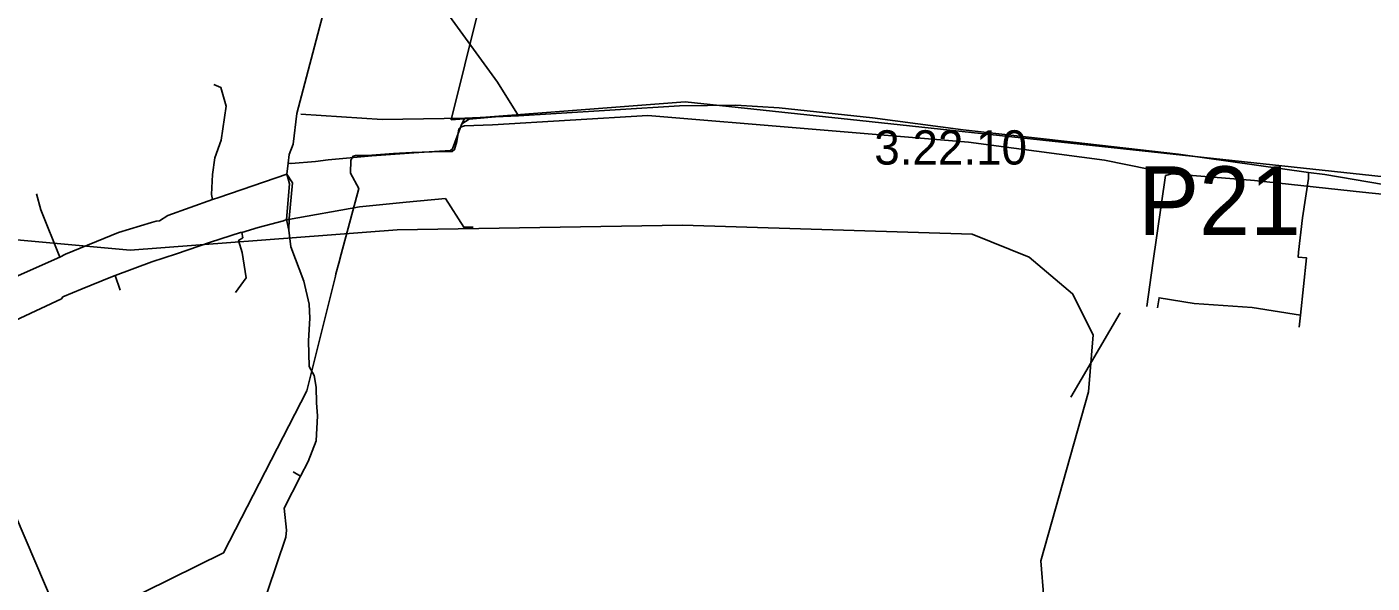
# Model space of a CAD drawing. Extents: x -662500 to -655523, y -1056000 to -1049993.
# Drawn here: x -659980.6 to -659685.9, y -1052099.4 to -1051977.6 of the extents above; entities that cross this region are included whole.
import ezdxf

# ---------------------------------------------------------------- set-up
doc = ezdxf.new("R2010")
doc.units = 0
for name, color, linetype in [('Vrstva 24', 7, 'Continuous'), ('Vrstva 45', 7, 'Continuous'), ('Vrstva 48', 7, 'Continuous'), ('Vrstva 61', 7, 'Continuous')]:
    doc.layers.add(name, color=color, linetype=linetype)

msp = doc.modelspace()

# ---------------------------------------------------------------- linework, layer by layer
at = {"layer": 'Vrstva 24'}
msp.add_lwpolyline([(-659753.8, -1052131.2), (-659756.5, -1052119), (-659758.5, -1052094.5), (-659748, -1052057.5), (-659747, -1052045), (-659751.5, -1052036), (-659761, -1052028), (-659773.5, -1052023), (-659837, -1052021), (-659899.5, -1052022), (-659958, -1052026.5), (-659996.5, -1052023), (-660000, -1052023), (-660013, -1052023)], dxfattribs=at)
at = {"layer": 'Vrstva 45'}
for p, q in [((-659884.7, -1051997.54), (-659872.93, -1051997.03)), ((-659884.7, -1051997.54), (-659872.93, -1051997.03)), ((-659872.93, -1051997.03), (-659865.86, -1051996.6)), ((-659872.93, -1051997.03), (-659865.86, -1051996.6)), ((-659872.93, -1051997.03), (-659865.86, -1051996.6)), ((-659872.93, -1051997.03), (-659865.86, -1051996.6)), ((-659872.93, -1051997.03), (-659865.86, -1051996.6)), ((-659872.93, -1051997.03), (-659865.86, -1051996.6)), ((-659884.7, -1051997.54), (-659885.32, -1051998.78)), ((-659884.7, -1051997.54), (-659885.32, -1051998.78)), ((-659884.75, -1051999.23), (-659878.58, -1051999.04)), ((-659884.75, -1051999.23), (-659878.58, -1051999.04)), ((-659895.81, -1052005.18), (-659890.25, -1052004.78)), ((-659895.81, -1052005.18), (-659890.25, -1052004.78)), ((-659923.68, -1052009.86), (-659923.4, -1052007.4)), ((-659923.68, -1052009.86), (-659923.4, -1052007.4)), ((-659923.68, -1052009.86), (-659923.4, -1052007.4)), ((-659923.68, -1052009.86), (-659923.4, -1052007.4)), ((-659917.4, -1052007.06), (-659922.75, -1052007.52)), ((-659917.4, -1052007.06), (-659922.75, -1052007.52)), ((-659923.12, -1052011.97), (-659923.72, -1052019.76)), ((-659923.12, -1052011.97), (-659923.72, -1052019.76)), ((-659923.41, -1052010.89), (-659923.68, -1052009.86)), ((-659923.41, -1052010.89), (-659923.68, -1052009.86)), ((-659922.46, -1052011.76), (-659923.17, -1052019.57)), ((-659922.46, -1052011.76), (-659923.17, -1052019.57)), ((-659699.84, -1052009.5), (-659696.21, -1052009.89)), ((-659699.84, -1052009.5), (-659696.21, -1052009.89)), ((-659699.84, -1052009.5), (-659696.21, -1052009.89)), ((-659699.84, -1052009.5), (-659696.21, -1052009.89)), ((-659699.84, -1052009.5), (-659696.21, -1052009.89)), ((-659699.84, -1052009.5), (-659696.21, -1052009.89)), ((-659960.58, -1052022.64), (-659953.35, -1052020.43)), ((-659960.58, -1052022.64), (-659953.35, -1052020.43)), ((-659923.28, -1052019.74), (-659923.72, -1052019.76)), ((-659923.28, -1052019.74), (-659923.72, -1052019.76)), ((-659923.72, -1052019.76), (-659923.23, -1052022.1)), ((-659923.72, -1052019.76), (-659923.23, -1052022.1)), ((-659701.15, -1052019.39), (-659702.01, -1052026.9)), ((-659701.15, -1052019.39), (-659702.01, -1052026.9)), ((-659940.39, -1052024.69), (-659933.85, -1052022.64)), ((-659940.39, -1052024.69), (-659933.85, -1052022.64)), ((-659953.23, -1052029.03), (-659947.88, -1052027.26)), ((-659953.23, -1052029.03), (-659947.88, -1052027.26)), ((-659912.3, -1052029.31), (-659911.76, -1052027.33)), ((-659912.3, -1052029.31), (-659911.76, -1052027.33)), ((-659968.48, -1052034.94), (-659962.26, -1052032.36)), ((-659968.48, -1052034.94), (-659962.26, -1052032.36)), ((-659961.3, -1052032.01), (-659960.16, -1052035.22)), ((-659961.3, -1052032.01), (-659960.16, -1052035.22)), ((-659751.87, -1052058.63), (-659741.12, -1052040.18)), ((-659751.87, -1052058.63), (-659741.12, -1052040.18)), ((-659701.87, -1052043.31), (-659701.59, -1052040.7)), ((-659701.87, -1052043.31), (-659701.59, -1052040.7)), ((-659922.31, -1052075.01), (-659920.64, -1052075.93)), ((-659922.31, -1052075.01), (-659920.64, -1052075.93))]:
    msp.add_line(p, q, dxfattribs=at)
for points in [[(-659921.51, -1051996.53), (-659915.5, -1051973.85), (-659913.41, -1051968.41), (-659910.3, -1051949.92), (-659910.26, -1051947.71)], [(-659921.51, -1051996.53), (-659915.5, -1051973.85), (-659913.41, -1051968.41), (-659910.3, -1051949.92), (-659910.26, -1051947.71)], [(-659899.23, -1051960.87), (-659898.67, -1051961.69), (-659888.06, -1051975.22), (-659877.52, -1051989.69), (-659872.93, -1051997.03)], [(-659899.23, -1051960.87), (-659898.67, -1051961.69), (-659888.06, -1051975.22), (-659877.52, -1051989.69), (-659872.93, -1051997.03)], [(-659899.23, -1051960.87), (-659898.67, -1051961.69), (-659888.06, -1051975.22), (-659877.52, -1051989.69), (-659872.93, -1051997.03)], [(-659899.23, -1051960.87), (-659898.67, -1051961.69), (-659888.06, -1051975.22), (-659877.52, -1051989.69), (-659872.93, -1051997.03)], [(-659939.92, -1052015.39), (-659940.14, -1052014.26), (-659939.96, -1052009.89), (-659939.41, -1052006.28), (-659938.03, -1052002.37), (-659936.97, -1051994.97), (-659938.15, -1051990.83), (-659939.7, -1051990.23)], [(-659939.92, -1052015.39), (-659940.14, -1052014.26), (-659939.96, -1052009.89), (-659939.41, -1052006.28), (-659938.03, -1052002.37), (-659936.97, -1051994.97), (-659938.15, -1051990.83), (-659939.7, -1051990.23)], [(-659923.4, -1052007.4), (-659923.13, -1052005.54), (-659922.3, -1052003.3), (-659921.51, -1051996.53)], [(-659923.4, -1052007.4), (-659923.13, -1052005.54), (-659922.3, -1052003.3), (-659921.51, -1051996.53)], [(-659920.6, -1051996.72), (-659902.81, -1051997.88), (-659884.7, -1051997.54)], [(-659920.6, -1051996.72), (-659902.81, -1051997.88), (-659884.7, -1051997.54)], [(-659870.66, -1051996.6), (-659883.71, -1051997.76), (-659885.32, -1051998.78)], [(-659870.66, -1051996.6), (-659883.71, -1051997.76), (-659885.32, -1051998.78)], [(-659878.58, -1051999.04), (-659844.57, -1051997.01), (-659774.33, -1052002.82), (-659744.5, -1052006.79), (-659729.75, -1052009.73)], [(-659878.58, -1051999.04), (-659844.57, -1051997.01), (-659774.33, -1052002.82), (-659744.5, -1052006.79), (-659729.75, -1052009.73)], [(-659865.86, -1051996.6), (-659837.64, -1051994.86), (-659825.32, -1051994.73), (-659815.8, -1051995.33), (-659795.38, -1051997.48), (-659775.52, -1052000.1), (-659751.37, -1052002.82), (-659728.29, -1052005.43), (-659699.84, -1052009.5)], [(-659865.86, -1051996.6), (-659837.64, -1051994.86), (-659825.32, -1051994.73), (-659815.8, -1051995.33), (-659795.38, -1051997.48), (-659775.52, -1052000.1), (-659751.37, -1052002.82), (-659728.29, -1052005.43), (-659699.84, -1052009.5)], [(-659865.86, -1051996.6), (-659837.64, -1051994.86), (-659825.32, -1051994.73), (-659815.8, -1051995.33), (-659795.38, -1051997.48), (-659775.52, -1052000.1), (-659751.37, -1052002.82), (-659728.29, -1052005.43), (-659699.84, -1052009.5)], [(-659865.86, -1051996.6), (-659837.64, -1051994.86), (-659825.32, -1051994.73), (-659815.8, -1051995.33), (-659795.38, -1051997.48), (-659775.52, -1052000.1), (-659751.37, -1052002.82), (-659728.29, -1052005.43), (-659699.84, -1052009.5)], [(-659865.86, -1051996.6), (-659837.64, -1051994.86), (-659825.32, -1051994.73), (-659815.8, -1051995.33), (-659795.38, -1051997.48), (-659775.52, -1052000.1), (-659751.37, -1052002.82), (-659728.29, -1052005.43), (-659699.84, -1052009.5)], [(-659865.86, -1051996.6), (-659837.64, -1051994.86), (-659825.32, -1051994.73), (-659815.8, -1051995.33), (-659795.38, -1051997.48), (-659775.52, -1052000.1), (-659751.37, -1052002.82), (-659728.29, -1052005.43), (-659699.84, -1052009.5)], [(-659885.32, -1051998.78), (-659886.32, -1052001.51), (-659887.35, -1052004.31), (-659887.79, -1052004.64), (-659890.25, -1052004.78), (-659895.81, -1052005.18), (-659905.06, -1052005.83), (-659914.59, -1052006.71), (-659917.4, -1052007.06), (-659922.75, -1052007.52), (-659923.4, -1052007.4)], [(-659885.32, -1051998.78), (-659886.32, -1052001.51), (-659887.35, -1052004.31), (-659887.79, -1052004.64), (-659890.25, -1052004.78), (-659895.81, -1052005.18), (-659905.06, -1052005.83), (-659914.59, -1052006.71), (-659917.4, -1052007.06), (-659922.75, -1052007.52), (-659923.4, -1052007.4)], [(-659885.32, -1051998.78), (-659886.32, -1052001.51), (-659887.35, -1052004.31), (-659887.79, -1052004.64), (-659890.25, -1052004.78), (-659895.81, -1052005.18), (-659905.06, -1052005.83), (-659914.59, -1052006.71), (-659917.4, -1052007.06), (-659922.75, -1052007.52), (-659923.4, -1052007.4)], [(-659885.32, -1051998.78), (-659886.32, -1052001.51), (-659887.35, -1052004.31), (-659887.79, -1052004.64), (-659890.25, -1052004.78), (-659895.81, -1052005.18), (-659905.06, -1052005.83), (-659914.59, -1052006.71), (-659917.4, -1052007.06), (-659922.75, -1052007.52), (-659923.4, -1052007.4)], [(-659884.75, -1051999.23), (-659885.64, -1051999.51), (-659885.95, -1051999.92), (-659886.42, -1052002.71), (-659886.95, -1052004.47), (-659887.41, -1052004.86), (-659888, -1052004.89), (-659891.85, -1052004.92), (-659896.26, -1052005.1), (-659900.28, -1052005.34), (-659905.97, -1052005.73), (-659908.63, -1052005.75), (-659909.15, -1052005.93), (-659909.68, -1052006.76), (-659909.7, -1052009.64)], [(-659884.75, -1051999.23), (-659885.64, -1051999.51), (-659885.95, -1051999.92), (-659886.42, -1052002.71), (-659886.95, -1052004.47), (-659887.41, -1052004.86), (-659888, -1052004.89), (-659891.85, -1052004.92), (-659896.26, -1052005.1), (-659900.28, -1052005.34), (-659905.97, -1052005.73), (-659908.63, -1052005.75), (-659909.15, -1052005.93), (-659909.68, -1052006.76), (-659909.7, -1052009.64)], [(-659923.68, -1052009.86), (-659938.56, -1052014.92), (-659939.92, -1052015.39)], [(-659923.68, -1052009.86), (-659938.56, -1052014.92), (-659939.92, -1052015.39)], [(-659923.72, -1052019.76), (-659923.12, -1052011.97), (-659923.41, -1052010.89)], [(-659923.72, -1052019.76), (-659923.12, -1052011.97), (-659923.41, -1052010.89)], [(-659923.23, -1052022.1), (-659923.17, -1052019.57), (-659922.46, -1052011.76), (-659923.68, -1052009.86)], [(-659923.23, -1052022.1), (-659923.17, -1052019.57), (-659922.46, -1052011.76), (-659923.68, -1052009.86)], [(-659911.76, -1052027.33), (-659907.93, -1052013), (-659909.7, -1052009.64)], [(-659911.76, -1052027.33), (-659907.93, -1052013), (-659909.7, -1052009.64)], [(-659729.75, -1052009.73), (-659731.13, -1052010.15), (-659733.95, -1052029.29), (-659735.21, -1052038.77)], [(-659729.75, -1052009.73), (-659731.13, -1052010.15), (-659733.95, -1052029.29), (-659735.21, -1052038.77)], [(-659672.38, -1052015.37), (-659688.02, -1052013.78), (-659711.64, -1052011.23), (-659729.75, -1052009.73)], [(-659672.38, -1052015.37), (-659688.02, -1052013.78), (-659711.64, -1052011.23), (-659729.75, -1052009.73)], [(-659701.59, -1052040.7), (-659700.28, -1052028.12), (-659702.1, -1052027.99), (-659702.01, -1052026.9), (-659701.15, -1052019.39), (-659699.82, -1052010.75), (-659699.84, -1052009.5)], [(-659701.59, -1052040.7), (-659700.28, -1052028.12), (-659702.1, -1052027.99), (-659702.01, -1052026.9), (-659701.15, -1052019.39), (-659699.82, -1052010.75), (-659699.84, -1052009.5)], [(-659696.21, -1052009.89), (-659683.37, -1052012.08), (-659680.79, -1052012.49), (-659675.63, -1052013.46), (-659674.22, -1052013.52), (-659653.56, -1052015.29), (-659620.75, -1052016.72), (-659579.74, -1052018.9), (-659534.75, -1052021.27), (-659514.48, -1052021.51), (-659479.83, -1052019.93)], [(-659696.21, -1052009.89), (-659683.37, -1052012.08), (-659680.79, -1052012.49), (-659675.63, -1052013.46), (-659674.22, -1052013.52), (-659653.56, -1052015.29), (-659620.75, -1052016.72), (-659579.74, -1052018.9), (-659534.75, -1052021.27), (-659514.48, -1052021.51), (-659479.83, -1052019.93)], [(-659696.21, -1052009.89), (-659683.37, -1052012.08), (-659680.79, -1052012.49), (-659675.63, -1052013.46), (-659674.22, -1052013.52), (-659653.56, -1052015.29), (-659620.75, -1052016.72), (-659579.74, -1052018.9), (-659534.75, -1052021.27), (-659514.48, -1052021.51), (-659479.83, -1052019.93)], [(-659696.21, -1052009.89), (-659683.37, -1052012.08), (-659680.79, -1052012.49), (-659675.63, -1052013.46), (-659674.22, -1052013.52), (-659653.56, -1052015.29), (-659620.75, -1052016.72), (-659579.74, -1052018.9), (-659534.75, -1052021.27), (-659514.48, -1052021.51), (-659479.83, -1052019.93)], [(-659696.21, -1052009.89), (-659683.37, -1052012.08), (-659680.79, -1052012.49), (-659675.63, -1052013.46), (-659674.22, -1052013.52), (-659653.56, -1052015.29), (-659620.75, -1052016.72), (-659579.74, -1052018.9), (-659534.75, -1052021.27), (-659514.48, -1052021.51), (-659479.83, -1052019.93)], [(-659696.21, -1052009.89), (-659683.37, -1052012.08), (-659680.79, -1052012.49), (-659675.63, -1052013.46), (-659674.22, -1052013.52), (-659653.56, -1052015.29), (-659620.75, -1052016.72), (-659579.74, -1052018.9), (-659534.75, -1052021.27), (-659514.48, -1052021.51), (-659479.83, -1052019.93)], [(-659973.41, -1052027.98), (-659977.59, -1052017.67), (-659978.53, -1052014.16)], [(-659973.41, -1052027.98), (-659977.59, -1052017.67), (-659978.53, -1052014.16)], [(-659882.82, -1052021.47), (-659884.89, -1052021.45), (-659888.91, -1052015.14), (-659897.52, -1052015.94), (-659907.73, -1052017), (-659923.28, -1052019.74)], [(-659882.82, -1052021.47), (-659884.89, -1052021.45), (-659888.91, -1052015.14), (-659897.52, -1052015.94), (-659907.73, -1052017), (-659923.28, -1052019.74)], [(-659939.92, -1052015.39), (-659949.73, -1052018.89), (-659951.54, -1052020.03), (-659952.3, -1052020.15), (-659953.35, -1052020.43), (-659960.58, -1052022.64), (-659972.18, -1052027.33), (-659973.41, -1052027.98)], [(-659939.92, -1052015.39), (-659949.73, -1052018.89), (-659951.54, -1052020.03), (-659952.3, -1052020.15), (-659953.35, -1052020.43), (-659960.58, -1052022.64), (-659972.18, -1052027.33), (-659973.41, -1052027.98)], [(-659933.53, -1052022.63), (-659929.98, -1052021.52), (-659924.42, -1052020.04), (-659923.72, -1052019.76)], [(-659933.53, -1052022.63), (-659929.98, -1052021.52), (-659924.42, -1052020.04), (-659923.72, -1052019.76)], [(-659933.53, -1052022.63), (-659933.85, -1052022.64), (-659940.39, -1052024.69), (-659947.88, -1052027.26), (-659953.23, -1052029.03), (-659961.3, -1052032.01)], [(-659933.53, -1052022.63), (-659933.85, -1052022.64), (-659940.39, -1052024.69), (-659947.88, -1052027.26), (-659953.23, -1052029.03), (-659961.3, -1052032.01)], [(-659933.53, -1052022.63), (-659933.33, -1052023.76), (-659934.25, -1052024.35), (-659933.47, -1052026.98), (-659932.6, -1052032.56), (-659934.9, -1052035.72)], [(-659933.53, -1052022.63), (-659933.33, -1052023.76), (-659934.25, -1052024.35), (-659933.47, -1052026.98), (-659932.6, -1052032.56), (-659934.9, -1052035.72)], [(-659923.23, -1052022.1), (-659922.8, -1052025.77), (-659919.91, -1052033.24), (-659918.77, -1052038.31), (-659918.6, -1052041.38), (-659918.94, -1052046.32), (-659918.76, -1052051.97), (-659917.7, -1052053.9), (-659917.21, -1052056.43), (-659917.17, -1052059.9), (-659916.92, -1052062.74), (-659917.27, -1052068.22), (-659919, -1052072.72), (-659920.64, -1052075.93)], [(-659923.23, -1052022.1), (-659922.8, -1052025.77), (-659919.91, -1052033.24), (-659918.77, -1052038.31), (-659918.6, -1052041.38), (-659918.94, -1052046.32), (-659918.76, -1052051.97), (-659917.7, -1052053.9), (-659917.21, -1052056.43), (-659917.17, -1052059.9), (-659916.92, -1052062.74), (-659917.27, -1052068.22), (-659919, -1052072.72), (-659920.64, -1052075.93)], [(-659923.23, -1052022.1), (-659922.8, -1052025.77), (-659919.91, -1052033.24), (-659918.77, -1052038.31), (-659918.6, -1052041.38), (-659918.94, -1052046.32), (-659918.76, -1052051.97), (-659917.7, -1052053.9), (-659917.21, -1052056.43), (-659917.17, -1052059.9), (-659916.92, -1052062.74), (-659917.27, -1052068.22), (-659919, -1052072.72), (-659920.64, -1052075.93)], [(-659923.23, -1052022.1), (-659922.8, -1052025.77), (-659919.91, -1052033.24), (-659918.77, -1052038.31), (-659918.6, -1052041.38), (-659918.94, -1052046.32), (-659918.76, -1052051.97), (-659917.7, -1052053.9), (-659917.21, -1052056.43), (-659917.17, -1052059.9), (-659916.92, -1052062.74), (-659917.27, -1052068.22), (-659919, -1052072.72), (-659920.64, -1052075.93)], [(-659973.41, -1052027.98), (-659985.07, -1052033.15), (-659991.06, -1052035.95), (-659998.22, -1052039.47), (-660005.46, -1052042.98)], [(-659973.41, -1052027.98), (-659985.07, -1052033.15), (-659991.06, -1052035.95), (-659998.22, -1052039.47), (-660005.46, -1052042.98)], [(-659913.04, -1052032.13), (-659912.93, -1052031.68), (-659912.3, -1052029.31)], [(-659913.04, -1052032.13), (-659912.93, -1052031.68), (-659912.3, -1052029.31)], [(-659991.2, -1052045.59), (-659973.05, -1052037.1), (-659972.73, -1052036.71), (-659968.48, -1052034.94), (-659962.26, -1052032.36), (-659961.3, -1052032.01)], [(-659991.2, -1052045.59), (-659973.05, -1052037.1), (-659972.73, -1052036.71), (-659968.48, -1052034.94), (-659962.26, -1052032.36), (-659961.3, -1052032.01)], [(-659966.88, -1052109.82), (-659960.64, -1052104.11), (-659937.52, -1052092.76), (-659919.32, -1052057.27), (-659913.04, -1052032.13)], [(-659966.88, -1052109.82), (-659960.64, -1052104.11), (-659937.52, -1052092.76), (-659919.32, -1052057.27), (-659913.04, -1052032.13)], [(-659701.59, -1052040.7), (-659712.2, -1052039.04), (-659724.91, -1052038.13), (-659732.55, -1052036.89), (-659732.9, -1052039.1)], [(-659701.59, -1052040.7), (-659712.2, -1052039.04), (-659724.91, -1052038.13), (-659732.55, -1052036.89), (-659732.9, -1052039.1)], [(-660014.2, -1052058.56), (-659996.89, -1052049.45), (-659992.05, -1052059.19), (-659985.67, -1052078.6), (-659971.85, -1052110.93), (-659966.88, -1052109.82)], [(-660014.2, -1052058.56), (-659996.89, -1052049.45), (-659992.05, -1052059.19), (-659985.67, -1052078.6), (-659971.85, -1052110.93), (-659966.88, -1052109.82)], [(-659987.17, -1052202.28), (-659976.05, -1052186.2), (-659970.46, -1052180.47), (-659940.04, -1052136.63), (-659939.88, -1052136.47), (-659936.03, -1052126.15), (-659935.15, -1052123.36), (-659930.77, -1052108.95), (-659927.94, -1052101.2), (-659923.86, -1052089.29), (-659923.75, -1052087.79), (-659924.23, -1052082.97), (-659920.64, -1052075.93)], [(-659987.17, -1052202.28), (-659976.05, -1052186.2), (-659970.46, -1052180.47), (-659940.04, -1052136.63), (-659939.88, -1052136.47), (-659936.03, -1052126.15), (-659935.15, -1052123.36), (-659930.77, -1052108.95), (-659927.94, -1052101.2), (-659923.86, -1052089.29), (-659923.75, -1052087.79), (-659924.23, -1052082.97), (-659920.64, -1052075.93)], [(-659987.17, -1052202.28), (-659976.05, -1052186.2), (-659970.46, -1052180.47), (-659940.04, -1052136.63), (-659939.88, -1052136.47), (-659936.03, -1052126.15), (-659935.15, -1052123.36), (-659930.77, -1052108.95), (-659927.94, -1052101.2), (-659923.86, -1052089.29), (-659923.75, -1052087.79), (-659924.23, -1052082.97), (-659920.64, -1052075.93)], [(-659987.17, -1052202.28), (-659976.05, -1052186.2), (-659970.46, -1052180.47), (-659940.04, -1052136.63), (-659939.88, -1052136.47), (-659936.03, -1052126.15), (-659935.15, -1052123.36), (-659930.77, -1052108.95), (-659927.94, -1052101.2), (-659923.86, -1052089.29), (-659923.75, -1052087.79), (-659924.23, -1052082.97), (-659920.64, -1052075.93)]]:
    msp.add_lwpolyline(points, dxfattribs=at)
at = {"layer": 'Vrstva 48'}
msp.add_lwpolyline([(-659878.72, -1051962.02), (-659887.64, -1051997.92), (-659836.43, -1051993.97), (-659800.18, -1051997.87), (-659681.2, -1052010.63)], dxfattribs=at)

# ---------------------------------------------------------------- texts
at = {"layer": 'Vrstva 24'}
msp.add_text('3.22.10', height=7.5, dxfattribs=at).set_placement((-659794.96, -1052007.73))
at = {"layer": 'Vrstva 61'}
msp.add_text('P21', height=15, dxfattribs=at).set_placement((-659737.17, -1052023.13))

doc.saveas('drawing.dxf')
